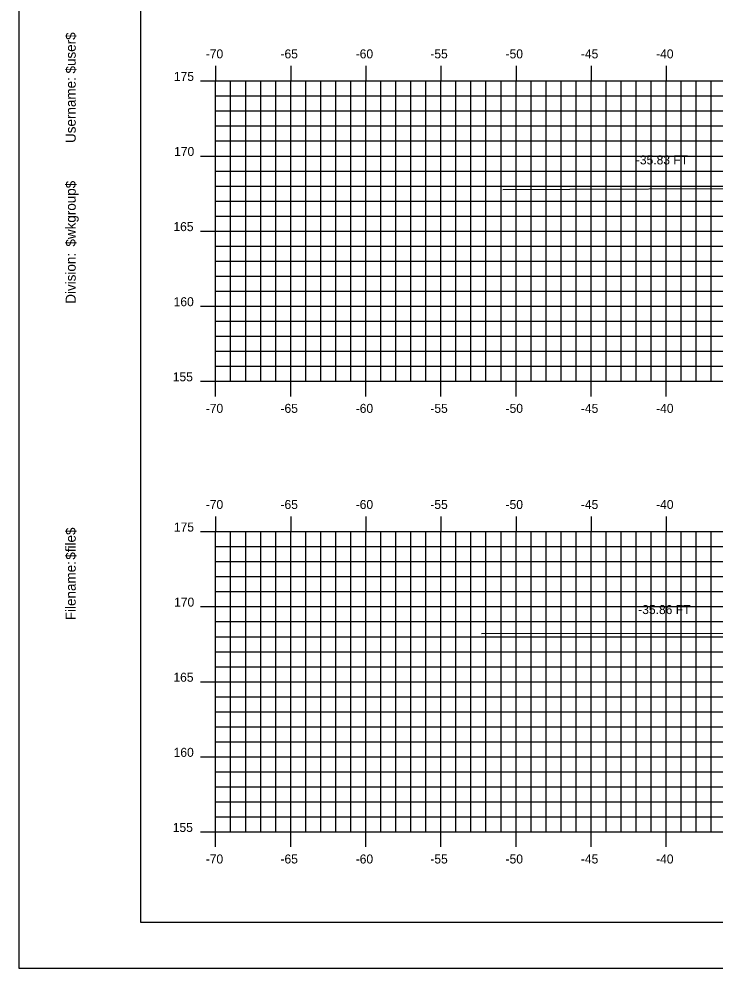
# Model space of a CAD drawing. Extents: x 1142089 to 1142259, y 608981 to 609091.
# Drawn here: x 1142089.4 to 1142135.8, y 608981.3 to 609044.5 of the extents above; entities that cross this region are included whole.
import ezdxf

# ---------------------------------------------------------------- set-up
doc = ezdxf.new("R2010")
doc.units = 0
for name, color, linetype in [('BORDER', 7, 'Continuous'), ('D_Text_Standard', 7, 'Continuous'), ('H_V ANNOTATION', 7, 'Continuous'), ('MAJOR', 7, 'Continuous'), ('MINOR', 7, 'Continuous'), ('PLOT BOUNDARY', 7, 'Continuous'), ('S_Roadway_Centerline', 7, 'Continuous')]:
    doc.layers.add(name, color=color, linetype=linetype)

msp = doc.modelspace()

# ---------------------------------------------------------------- linework, layer by layer
at = {"layer": 'BORDER'}
msp.add_lwpolyline([(1142097.541, 608984.335), (1142257.541, 608984.335), (1142257.541, 609089.335), (1142097.541, 609089.335)], close=True, dxfattribs=at)
at = {"layer": 'MAJOR'}
for p, q in [((1142102.54, 609041.337), (1142102.54, 609040.335)), ((1142107.54, 609041.337), (1142107.54, 609040.335)), ((1142112.54, 609041.337), (1142112.54, 609040.335)), ((1142117.54, 609041.337), (1142117.54, 609040.335)), ((1142122.54, 609041.337), (1142122.54, 609040.335)), ((1142127.54, 609041.337), (1142127.54, 609040.335)), ((1142132.54, 609041.337), (1142132.54, 609040.335)), ((1142101.538, 609040.335), (1142102.54, 609040.335)), ((1142102.54, 609040.335), (1142242.54, 609040.335)), ((1142102.54, 609020.335), (1142102.54, 609040.335)), ((1142102.54, 609020.335), (1142102.54, 609040.335)), ((1142102.54, 609040.335), (1142242.54, 609040.335)), ((1142107.54, 609020.335), (1142107.54, 609040.335)), ((1142112.54, 609020.335), (1142112.54, 609040.335)), ((1142117.54, 609020.335), (1142117.54, 609040.335)), ((1142122.54, 609020.335), (1142122.54, 609040.335)), ((1142127.54, 609020.335), (1142127.54, 609040.335)), ((1142132.54, 609020.335), (1142132.54, 609040.335)), ((1142101.538, 609035.335), (1142102.54, 609035.335)), ((1142102.54, 609035.335), (1142242.54, 609035.335)), ((1142101.538, 609030.335), (1142102.54, 609030.335)), ((1142102.54, 609030.335), (1142242.54, 609030.335)), ((1142101.538, 609025.335), (1142102.54, 609025.335)), ((1142102.54, 609025.335), (1142242.54, 609025.335)), ((1142101.538, 609020.335), (1142102.54, 609020.335)), ((1142102.54, 609020.335), (1142242.54, 609020.335)), ((1142102.54, 609020.335), (1142242.54, 609020.335)), ((1142102.54, 609019.333), (1142102.54, 609020.335)), ((1142107.54, 609019.333), (1142107.54, 609020.335)), ((1142112.54, 609019.333), (1142112.54, 609020.335)), ((1142117.54, 609019.333), (1142117.54, 609020.335)), ((1142122.54, 609019.333), (1142122.54, 609020.335)), ((1142127.54, 609019.333), (1142127.54, 609020.335)), ((1142132.54, 609019.333), (1142132.54, 609020.335)), ((1142102.54, 609011.337), (1142102.54, 609010.335)), ((1142107.54, 609011.337), (1142107.54, 609010.335)), ((1142112.54, 609011.337), (1142112.54, 609010.335)), ((1142117.54, 609011.337), (1142117.54, 609010.335)), ((1142122.54, 609011.337), (1142122.54, 609010.335)), ((1142127.54, 609011.337), (1142127.54, 609010.335)), ((1142132.54, 609011.337), (1142132.54, 609010.335)), ((1142101.538, 609010.335), (1142102.54, 609010.335)), ((1142102.54, 609010.335), (1142242.54, 609010.335)), ((1142102.54, 608990.335), (1142102.54, 609010.335)), ((1142102.54, 608990.335), (1142102.54, 609010.335)), ((1142102.54, 609010.335), (1142242.54, 609010.335)), ((1142107.54, 608990.335), (1142107.54, 609010.335)), ((1142112.54, 608990.335), (1142112.54, 609010.335)), ((1142117.54, 608990.335), (1142117.54, 609010.335)), ((1142122.54, 608990.335), (1142122.54, 609010.335)), ((1142127.54, 608990.335), (1142127.54, 609010.335)), ((1142132.54, 608990.335), (1142132.54, 609010.335)), ((1142101.538, 609005.335), (1142102.54, 609005.335)), ((1142102.54, 609005.335), (1142242.54, 609005.335)), ((1142101.538, 609000.335), (1142102.54, 609000.335)), ((1142102.54, 609000.335), (1142242.54, 609000.335)), ((1142101.538, 608995.335), (1142102.54, 608995.335)), ((1142102.54, 608995.335), (1142242.54, 608995.335)), ((1142101.538, 608990.335), (1142102.54, 608990.335)), ((1142102.54, 608990.335), (1142242.54, 608990.335)), ((1142102.54, 608990.335), (1142242.54, 608990.335)), ((1142102.54, 608989.333), (1142102.54, 608990.335)), ((1142107.54, 608989.333), (1142107.54, 608990.335)), ((1142112.54, 608989.333), (1142112.54, 608990.335)), ((1142117.54, 608989.333), (1142117.54, 608990.335)), ((1142122.54, 608989.333), (1142122.54, 608990.335)), ((1142127.54, 608989.333), (1142127.54, 608990.335)), ((1142132.54, 608989.333), (1142132.54, 608990.335))]:
    msp.add_line(p, q, dxfattribs=at)
at = {"layer": 'MINOR'}
for p, q in [((1142103.54, 609020.335), (1142103.54, 609040.335)), ((1142104.54, 609020.335), (1142104.54, 609040.335)), ((1142105.54, 609020.335), (1142105.54, 609040.335)), ((1142106.54, 609020.335), (1142106.54, 609040.335)), ((1142108.54, 609020.335), (1142108.54, 609040.335)), ((1142109.54, 609020.335), (1142109.54, 609040.335)), ((1142110.54, 609020.335), (1142110.54, 609040.335)), ((1142111.54, 609020.335), (1142111.54, 609040.335)), ((1142113.54, 609020.335), (1142113.54, 609040.335)), ((1142114.54, 609020.335), (1142114.54, 609040.335)), ((1142115.54, 609020.335), (1142115.54, 609040.335)), ((1142116.54, 609020.335), (1142116.54, 609040.335)), ((1142118.54, 609020.335), (1142118.54, 609040.335)), ((1142119.54, 609020.335), (1142119.54, 609040.335)), ((1142120.54, 609020.335), (1142120.54, 609040.335)), ((1142121.54, 609020.335), (1142121.54, 609040.335)), ((1142123.54, 609020.335), (1142123.54, 609040.335)), ((1142124.54, 609020.335), (1142124.54, 609040.335)), ((1142125.54, 609020.335), (1142125.54, 609040.335)), ((1142126.54, 609020.335), (1142126.54, 609040.335)), ((1142128.54, 609020.335), (1142128.54, 609040.335)), ((1142129.54, 609020.335), (1142129.54, 609040.335)), ((1142130.54, 609020.335), (1142130.54, 609040.335)), ((1142131.54, 609020.335), (1142131.54, 609040.335)), ((1142133.54, 609020.335), (1142133.54, 609040.335)), ((1142134.54, 609020.335), (1142134.54, 609040.335)), ((1142135.54, 609020.335), (1142135.54, 609040.335)), ((1142102.54, 609039.335), (1142242.54, 609039.335)), ((1142102.54, 609039.335), (1142103.542, 609039.335)), ((1142102.54, 609038.335), (1142242.54, 609038.335)), ((1142102.54, 609038.335), (1142103.542, 609038.335)), ((1142102.54, 609037.335), (1142242.54, 609037.335)), ((1142102.54, 609037.335), (1142103.542, 609037.335)), ((1142102.54, 609036.335), (1142242.54, 609036.335)), ((1142102.54, 609036.335), (1142103.542, 609036.335)), ((1142102.54, 609034.335), (1142242.54, 609034.335)), ((1142102.54, 609034.335), (1142103.542, 609034.335)), ((1142102.54, 609033.335), (1142242.54, 609033.335)), ((1142102.54, 609033.335), (1142103.542, 609033.335)), ((1142102.54, 609032.335), (1142242.54, 609032.335)), ((1142102.54, 609032.335), (1142103.542, 609032.335)), ((1142102.54, 609031.335), (1142242.54, 609031.335)), ((1142102.54, 609031.335), (1142103.542, 609031.335)), ((1142102.54, 609029.335), (1142242.54, 609029.335)), ((1142102.54, 609029.335), (1142103.542, 609029.335)), ((1142102.54, 609028.335), (1142242.54, 609028.335)), ((1142102.54, 609028.335), (1142103.542, 609028.335)), ((1142102.54, 609027.335), (1142242.54, 609027.335)), ((1142102.54, 609027.335), (1142103.542, 609027.335)), ((1142102.54, 609026.335), (1142242.54, 609026.335)), ((1142102.54, 609026.335), (1142103.542, 609026.335)), ((1142102.54, 609024.335), (1142242.54, 609024.335)), ((1142102.54, 609024.335), (1142103.542, 609024.335)), ((1142102.54, 609023.335), (1142242.54, 609023.335)), ((1142102.54, 609023.335), (1142103.542, 609023.335)), ((1142102.54, 609022.335), (1142242.54, 609022.335)), ((1142102.54, 609022.335), (1142103.542, 609022.335)), ((1142102.54, 609021.335), (1142242.54, 609021.335)), ((1142102.54, 609021.335), (1142103.542, 609021.335)), ((1142103.54, 608990.335), (1142103.54, 609010.335)), ((1142104.54, 608990.335), (1142104.54, 609010.335)), ((1142105.54, 608990.335), (1142105.54, 609010.335)), ((1142106.54, 608990.335), (1142106.54, 609010.335)), ((1142108.54, 608990.335), (1142108.54, 609010.335)), ((1142109.54, 608990.335), (1142109.54, 609010.335)), ((1142110.54, 608990.335), (1142110.54, 609010.335)), ((1142111.54, 608990.335), (1142111.54, 609010.335)), ((1142113.54, 608990.335), (1142113.54, 609010.335)), ((1142114.54, 608990.335), (1142114.54, 609010.335)), ((1142115.54, 608990.335), (1142115.54, 609010.335)), ((1142116.54, 608990.335), (1142116.54, 609010.335)), ((1142118.54, 608990.335), (1142118.54, 609010.335)), ((1142119.54, 608990.335), (1142119.54, 609010.335)), ((1142120.54, 608990.335), (1142120.54, 609010.335)), ((1142121.54, 608990.335), (1142121.54, 609010.335)), ((1142123.54, 608990.335), (1142123.54, 609010.335)), ((1142124.54, 608990.335), (1142124.54, 609010.335)), ((1142125.54, 608990.335), (1142125.54, 609010.335)), ((1142126.54, 608990.335), (1142126.54, 609010.335)), ((1142128.54, 608990.335), (1142128.54, 609010.335)), ((1142129.54, 608990.335), (1142129.54, 609010.335)), ((1142130.54, 608990.335), (1142130.54, 609010.335)), ((1142131.54, 608990.335), (1142131.54, 609010.335)), ((1142133.54, 608990.335), (1142133.54, 609010.335)), ((1142134.54, 608990.335), (1142134.54, 609010.335)), ((1142135.54, 608990.335), (1142135.54, 609010.335)), ((1142102.54, 609009.335), (1142242.54, 609009.335)), ((1142102.54, 609009.335), (1142103.542, 609009.335)), ((1142102.54, 609008.335), (1142242.54, 609008.335)), ((1142102.54, 609008.335), (1142103.542, 609008.335)), ((1142102.54, 609007.335), (1142242.54, 609007.335)), ((1142102.54, 609007.335), (1142103.542, 609007.335)), ((1142102.54, 609006.335), (1142242.54, 609006.335)), ((1142102.54, 609006.335), (1142103.542, 609006.335)), ((1142102.54, 609004.335), (1142242.54, 609004.335)), ((1142102.54, 609004.335), (1142103.542, 609004.335)), ((1142102.54, 609003.335), (1142242.54, 609003.335)), ((1142102.54, 609003.335), (1142103.542, 609003.335)), ((1142102.54, 609002.335), (1142242.54, 609002.335)), ((1142102.54, 609002.335), (1142103.542, 609002.335)), ((1142102.54, 609001.335), (1142242.54, 609001.335)), ((1142102.54, 609001.335), (1142103.542, 609001.335)), ((1142102.54, 608999.335), (1142242.54, 608999.335)), ((1142102.54, 608999.335), (1142103.542, 608999.335)), ((1142102.54, 608998.335), (1142242.54, 608998.335)), ((1142102.54, 608998.335), (1142103.542, 608998.335)), ((1142102.54, 608997.335), (1142242.54, 608997.335)), ((1142102.54, 608997.335), (1142103.542, 608997.335)), ((1142102.54, 608996.335), (1142242.54, 608996.335)), ((1142102.54, 608996.335), (1142103.542, 608996.335)), ((1142102.54, 608994.335), (1142242.54, 608994.335)), ((1142102.54, 608994.335), (1142103.542, 608994.335)), ((1142102.54, 608993.335), (1142242.54, 608993.335)), ((1142102.54, 608993.335), (1142103.542, 608993.335)), ((1142102.54, 608992.335), (1142242.54, 608992.335)), ((1142102.54, 608992.335), (1142103.542, 608992.335)), ((1142102.54, 608991.335), (1142242.54, 608991.335)), ((1142102.54, 608991.335), (1142103.542, 608991.335))]:
    msp.add_line(p, q, dxfattribs=at)
at = {"layer": 'PLOT BOUNDARY'}
msp.add_lwpolyline([(1142089.447, 608981.276), (1142259.447, 608981.276), (1142259.447, 609091.276), (1142089.447, 609091.276)], close=True, dxfattribs=at)
at = {"layer": 'S_Roadway_Centerline'}
for points in [[(1142121.671, 609033.112), (1142126.127, 609033.122), (1142147.112, 609033.221), (1142148.27, 609032.961), (1142152.957, 609031.847), (1142153.787, 609031.981), (1142155.823, 609032.494), (1142156.613, 609032.611), (1142159.401, 609032.97), (1142168.323, 609033.066), (1142171.191, 609033.079), (1142179.536, 609032.919), (1142182.26, 609032.89), (1142183, 609032.834), (1142186.686, 609032.455), (1142188.804, 609032.159), (1142190.283, 609031.867), (1142191.191, 609032.024), (1142195.319, 609032.212), (1142205.426, 609032.209), (1142222.534, 609032.153)], [(1142120.248, 609003.54), (1142140.088, 609003.572), (1142147.837, 609003.464), (1142152.153, 609002.5), (1142153.465, 609002.339), (1142154.47, 609002.585), (1142157.194, 609003.025), (1142158.087, 609003.093), (1142160.552, 609003.459), (1142163.514, 609003.498), (1142172.183, 609003.534), (1142180.268, 609003.447), (1142183.249, 609003.394), (1142185.379, 609003.23), (1142186.373, 609003.17), (1142186.402, 609003.118), (1142187.497, 609002.831), (1142191.74, 609001.996), (1142192.511, 609002.174), (1142195.062, 609002.623), (1142212.721, 609002.317), (1142224.423, 609002.225)]]:
    msp.add_lwpolyline(points, dxfattribs=at)

# ---------------------------------------------------------------- texts
at = {"layer": 'BORDER'}
for s, p in [('$user$', (1142093.225, 609040.827)), ('Username:', (1142093.225, 609036.203)), ('$wkgroup$', (1142093.225, 609029.305)), ('Division:', (1142093.225, 609025.501)), ('$file$', (1142093.225, 609008.461)), ('Filename:', (1142093.225, 609004.433))]:
    msp.add_text(s, height=0.6696, rotation=90, dxfattribs=at).set_placement(p)
at = {"layer": 'D_Text_Standard'}
for s, p in [('-35.83 FT', (1142130.519, 609034.776)), ('-35.86 FT', (1142130.676, 609004.84))]:
    msp.add_text(s, height=0.6, dxfattribs=at).set_placement(p)
at = {"layer": 'H_V ANNOTATION'}
for s, p in [('-70', (1142101.882, 609041.835)), ('-65', (1142106.858, 609041.835)), ('-60', (1142111.866, 609041.835)), ('-55', (1142116.836, 609041.835)), ('-50', (1142121.844, 609041.835)), ('-45', (1142126.858, 609041.835)), ('-40', (1142131.866, 609041.835)), ('175', (1142099.761, 609040.335)), ('170', (1142099.777, 609035.335)), ('165', (1142099.729, 609030.335)), ('160', (1142099.745, 609025.335)), ('155', (1142099.686, 609020.335)), ('-70', (1142101.882, 609018.235)), ('-65', (1142106.858, 609018.235)), ('-60', (1142111.866, 609018.235)), ('-55', (1142116.836, 609018.235)), ('-50', (1142121.844, 609018.235)), ('-45', (1142126.858, 609018.235)), ('-40', (1142131.866, 609018.235)), ('-70', (1142101.882, 609011.835)), ('-65', (1142106.858, 609011.835)), ('-60', (1142111.866, 609011.835)), ('-55', (1142116.836, 609011.835)), ('-50', (1142121.844, 609011.835)), ('-45', (1142126.858, 609011.835)), ('-40', (1142131.866, 609011.835)), ('175', (1142099.761, 609010.335)), ('170', (1142099.777, 609005.335)), ('165', (1142099.729, 609000.335)), ('160', (1142099.745, 608995.335)), ('155', (1142099.686, 608990.335)), ('-70', (1142101.882, 608988.235)), ('-65', (1142106.858, 608988.235)), ('-60', (1142111.866, 608988.235)), ('-55', (1142116.836, 608988.235)), ('-50', (1142121.844, 608988.235)), ('-45', (1142126.858, 608988.235)), ('-40', (1142131.866, 608988.235))]:
    msp.add_text(s, height=0.6, dxfattribs=at).set_placement(p)
at = {"layer": 'MAJOR'}
for p in [(1142102.536, 609020.335), (1142102.536, 608990.335)]:
    msp.add_text('-', height=0.006, dxfattribs=at).set_placement(p)

doc.saveas('drawing.dxf')
